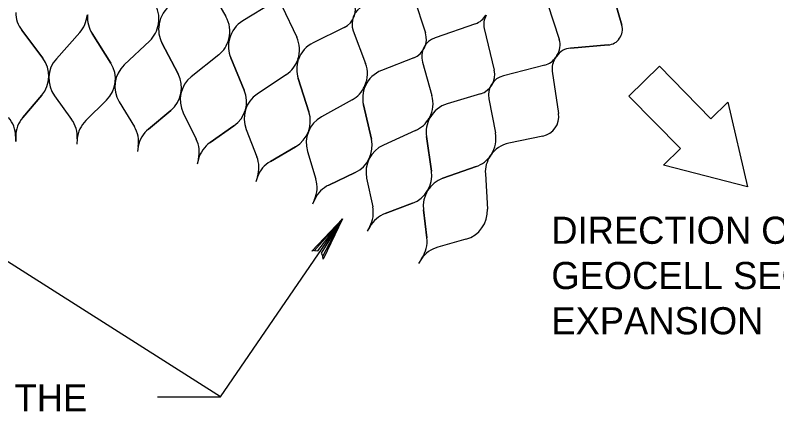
# Model space of a CAD drawing. Extents: x 638850 to 644908, y 297188 to 298900.
# Drawn here: x 639845 to 639929, y 297601.9 to 297645.7 of the extents above; entities that cross this region are included whole.
import ezdxf

# ---------------------------------------------------------------- set-up
doc = ezdxf.new("R2010")
doc.units = 0
for name, color, linetype in [('1', 7, 'Continuous'), ('5', 7, 'Continuous'), ('50', 7, 'Continuous'), ('9', 7, 'Continuous')]:
    doc.layers.add(name, color=color, linetype=linetype)

msp = doc.modelspace()

# ---------------------------------------------------------------- linework, layer by layer
at = {"layer": '1'}
for p, q in [((639912.726, 297636.791), (639916.097, 297640.09)), ((639916.097, 297640.09), (639921.772, 297634.291)), ((639918.401, 297630.992), (639912.726, 297636.791)), ((639921.772, 297634.291), (639923.631, 297636.109)), ((639923.631, 297636.109), (639925.827, 297626.776)), ((639916.543, 297629.173), (639918.401, 297630.992)), ((639925.827, 297626.776), (639916.543, 297629.173)), ((639867.623, 297603.567), (639828.475, 297628.426)), ((639867.623, 297603.567), (639881.085, 297623.21))]:
    msp.add_line(p, q, dxfattribs=at)
msp.add_lwpolyline([(639877.999, 297619.732), (639878.372, 297619.685), (639881.085, 297623.21), (639877.999, 297619.732), (639877.698, 297619.651), (639881.085, 297623.21), (639878.757, 297619.425), (639878.938, 297619.105), (639881.085, 297623.21), (639878.979, 297618.774), (639878.938, 297619.105)], dxfattribs=at)
at = {"layer": '5'}
for p, q in [((639866.298, 297648.885), (639868.226, 297645.577)), ((639910.637, 297649.22), (639911.94, 297644.624)), ((639888.786, 297648.253), (639890.254, 297643.762)), ((639873.371, 297647.079), (639870.093, 297645.101)), ((639874.398, 297646.77), (639876.043, 297643.313)), ((639903.722, 297647.025), (639905.018, 297643.066)), ((639852.903, 297645.762), (639852.898, 297645.702)), ((639852.967, 297645.757), (639852.962, 297645.697)), ((639860.789, 297644.78), (639860.779, 297644.721)), ((639860.853, 297644.77), (639860.843, 297644.711)), ((639895.783, 297644.79), (639891.322, 297643.233)), ((639845.682, 297644.075), (639848.022, 297640.978)), ((639852.089, 297643.816), (639849.507, 297640.918)), ((639881.295, 297644.379), (639877.864, 297642.682)), ((639882.293, 297643.985), (639883.642, 297640.402)), ((639896.755, 297644.258), (639897.841, 297639.659)), ((639853.452, 297643.704), (639855.524, 297640.422)), ((639868.566, 297643.142), (639868.551, 297643.084)), ((639868.628, 297643.126), (639868.613, 297643.068)), ((639859.815, 297642.91), (639856.999, 297640.238)), ((639861.164, 297642.684), (639862.954, 297639.239)), ((639910.423, 297642.436), (639906.272, 297642.095)), ((639867.438, 297641.359), (639864.409, 297638.932)), ((639868.763, 297641.021), (639870.259, 297637.439)), ((639876.177, 297640.858), (639876.158, 297640.801)), ((639876.238, 297640.837), (639876.218, 297640.78)), ((639888.966, 297641.024), (639885.404, 297639.621)), ((639889.927, 297640.549), (639890.972, 297636.866)), ((639904.653, 297641.078), (639904.587, 297640.979)), ((639904.776, 297641.279), (639904.644, 297641.08)), ((639904.719, 297641.178), (639904.653, 297641.078)), ((639903.437, 297640.221), (639898.861, 297639.043)), ((639874.904, 297639.176), (639871.682, 297637.011)), ((639904.264, 297639.533), (639904.954, 297634.859)), ((639876.196, 297638.728), (639877.387, 297635.033)), ((639883.571, 297637.944), (639883.547, 297637.89)), ((639883.63, 297637.918), (639883.605, 297637.864)), ((639847.897, 297636.876), (639845.8, 297634.425)), ((639849.301, 297636.819), (639851.193, 297634.207)), ((639855.057, 297636.344), (639852.762, 297634.078)), ((639882.162, 297636.375), (639878.77, 297634.488)), ((639896.329, 297637.04), (639892.662, 297635.939)), ((639897.247, 297636.485), (639897.979, 297632.727)), ((639856.45, 297636.17), (639858.118, 297633.41)), ((639883.412, 297635.82), (639884.288, 297632.039)), ((639862.147, 297635.216), (639859.67, 297633.149)), ((639863.521, 297634.925), (639864.951, 297632.035)), ((639890.695, 297634.422), (639890.666, 297634.37)), ((639890.751, 297634.391), (639890.722, 297634.339)), ((639869.117, 297633.497), (639866.476, 297631.645)), ((639870.462, 297633.093), (639871.645, 297630.092)), ((639889.159, 297632.976), (639885.621, 297631.38)), ((639845.011, 297632.346), (639845.017, 297631.758)), ((639845.022, 297632.347), (639845.017, 297631.758)), ((639851.801, 297632.073), (639851.758, 297631.486)), ((639851.813, 297632.072), (639851.758, 297631.486)), ((639890.358, 297632.319), (639890.915, 297628.477)), ((639903.224, 297632.378), (639899.476, 297631.594)), ((639858.545, 297631.232), (639858.453, 297630.65)), ((639858.556, 297631.23), (639858.453, 297630.65)), ((639875.919, 297631.201), (639873.133, 297629.577)), ((639877.226, 297630.685), (639878.153, 297627.596)), ((639865.194, 297629.829), (639865.054, 297629.257)), ((639865.206, 297629.826), (639865.054, 297629.257)), ((639897.44, 297630.215), (639897.407, 297630.165)), ((639895.847, 297629.004), (639892.188, 297627.709)), ((639871.703, 297627.874), (639871.516, 297627.316)), ((639871.714, 297627.87), (639871.516, 297627.316)), ((639882.505, 297628.343), (639879.592, 297626.958)), ((639896.872, 297628.184), (639897.099, 297624.309)), ((639883.764, 297627.72), (639884.43, 297624.564)), ((639878.025, 297625.381), (639877.792, 297624.84)), ((639878.036, 297625.376), (639877.792, 297624.84)), ((639888.828, 297624.944), (639885.81, 297623.807)), ((639890.031, 297624.217), (639890.416, 297621.128)), ((639884.116, 297622.367), (639883.838, 297621.848)), ((639884.126, 297622.361), (639883.838, 297621.848)), ((639894.719, 297620.966), (639891.614, 297620.091)), ((639889.813, 297618.794), (639889.483, 297618.307))]:
    msp.add_line(p, q, dxfattribs=at)
for centre, radius, start, end in [((639857.595, 297645.318), 3.24, 350.44021, 35.04845), ((639880.318, 297646.356), 2.206, 296.31108, 22.90015), ((639864.048, 297644.237), 3.24, 125.91822, 170.52646), ((639884.357, 297644.763), 2.206, 114.04867, 200.63774), ((639848.267, 297646.028), 3.24, 180.1336, 217.07193), ((639849.67, 297645.971), 3.24, 318.30545, 355.24378), ((639856.191, 297645.433), 3.24, 175.33003, 212.26836), ((639865.427, 297643.946), 3.24, 345.63664, 30.24488), ((639895.102, 297646.743), 2.068, 289.2451, 331.22593), ((639898.767, 297644.733), 2.068, 151.31218, 193.29301), ((639857.585, 297645.259), 3.24, 313.50188, 350.44021), ((639864.038, 297644.178), 3.24, 170.52646, 207.46479), ((639871.767, 297642.327), 3.24, 121.11465, 165.72289), ((639910.282, 297644.154), 1.723, 274.70429, 15.82869), ((639865.412, 297643.888), 3.24, 308.69831, 345.63664), ((639871.753, 297642.269), 3.24, 165.72289, 202.66122), ((639873.117, 297641.921), 3.24, 340.83307, 25.44131), ((639888.157, 297643.077), 2.206, 291.50751, 18.09658), ((639892.049, 297641.151), 2.206, 109.2451, 195.83416), ((639903.053, 297642.422), 2.068, 326.42236, 18.13587), ((639879.299, 297639.778), 3.24, 116.31108, 160.91932), ((639906.441, 297640.034), 2.068, 94.70429, 146.4178), ((639845.409, 297639.004), 3.274, 319.44945, 37.07193), ((639851.952, 297638.74), 3.274, 138.30545, 215.92793), ((639873.098, 297641.865), 3.24, 303.89474, 340.83307), ((639879.28, 297639.721), 3.24, 160.91932, 197.85765), ((639902.922, 297642.224), 2.068, 284.44152, 326.42236), ((639906.31, 297639.835), 2.068, 146.4178, 188.39863), ((639852.756, 297638.674), 3.274, 314.64588, 32.26836), ((639859.253, 297637.863), 3.274, 133.50188, 211.12436), ((639880.611, 297639.261), 3.24, 336.0295, 20.63773), ((639886.592, 297636.607), 3.24, 111.50751, 156.11575), ((639895.695, 297639.152), 2.206, 286.70394, 13.29301), ((639860.049, 297637.729), 3.274, 309.84231, 27.46479), ((639866.456, 297636.377), 3.274, 128.69831, 206.32079), ((639899.412, 297636.907), 2.206, 104.44153, 191.03059), ((639867.237, 297636.178), 3.274, 305.03874, 22.66122), ((639880.586, 297639.206), 3.24, 299.09117, 336.0295), ((639886.567, 297636.552), 3.24, 156.11575, 193.05408), ((639873.508, 297634.294), 3.274, 123.89474, 201.51722), ((639887.855, 297635.982), 3.24, 331.22593, 15.83416), ((639893.593, 297632.836), 3.24, 106.70394, 151.31217), ((639874.27, 297634.029), 3.274, 300.23517, 17.85765), ((639902.772, 297634.537), 2.206, 281.80956, 8.39863), ((639841.771, 297632.309), 3.24, 0.66838, 40.7315), ((639848.262, 297632.319), 3.24, 139.44945, 179.51256), ((639848.57, 297632.307), 3.24, 355.86481, 35.92793), ((639855.039, 297631.773), 3.24, 134.64588, 174.70899), ((639880.361, 297631.627), 3.274, 119.09117, 196.71365), ((639887.826, 297635.929), 3.24, 294.2876, 331.22593), ((639893.564, 297632.784), 3.24, 151.31218, 188.2505), ((639855.344, 297631.735), 3.24, 351.06124, 31.12436), ((639861.746, 297630.662), 3.24, 129.84231, 169.90542), ((639862.047, 297630.598), 3.24, 346.25767, 26.32079), ((639881.099, 297631.3), 3.274, 295.4316, 13.05408), ((639894.799, 297632.107), 3.24, 326.42236, 11.03059), ((639868.336, 297628.993), 3.24, 125.03874, 165.10185), ((639886.967, 297628.396), 3.274, 114.2876, 191.91008), ((639900.139, 297628.423), 3.24, 101.80956, 146.4178), ((639868.631, 297628.904), 3.24, 341.4541, 21.51722), ((639874.764, 297626.778), 3.24, 120.23517, 160.29828), ((639894.766, 297632.058), 3.24, 289.48403, 326.42235), ((639900.106, 297628.373), 3.24, 146.4178, 183.35613), ((639887.675, 297628.008), 3.274, 290.62803, 8.25051), ((639875.051, 297626.665), 3.24, 336.65053, 16.71365), ((639893.28, 297624.622), 3.274, 109.48403, 187.10651), ((639880.983, 297624.032), 3.24, 115.4316, 155.49471), ((639881.26, 297623.895), 3.24, 331.84696, 11.91008), ((639886.951, 297620.775), 3.24, 110.62803, 150.69114), ((639893.831, 297624.117), 3.274, 285.73365, 3.35613), ((639887.201, 297620.727), 3.24, 325.80132, 7.10651), ((639892.493, 297616.973), 3.24, 105.73365, 145.79676)]:
    msp.add_arc(centre, radius, start, end, dxfattribs=at)
at = {"layer": '50'}
for p, q in [((639911.94, 297644.624), (639910.637, 297649.22)), ((639903.722, 297647.025), (639905.018, 297643.066)), ((639852.962, 297645.697), (639852.898, 297645.702)), ((639860.843, 297644.711), (639860.779, 297644.721)), ((639848.022, 297640.978), (639845.682, 297644.075)), ((639852.089, 297643.816), (639849.507, 297640.918)), ((639855.524, 297640.422), (639853.452, 297643.704)), ((639868.613, 297643.068), (639868.551, 297643.084)), ((639859.815, 297642.91), (639856.999, 297640.238)), ((639862.954, 297639.239), (639861.164, 297642.684)), ((639906.272, 297642.095), (639910.423, 297642.436)), ((639867.438, 297641.359), (639864.409, 297638.932)), ((639870.259, 297637.439), (639868.763, 297641.021)), ((639876.218, 297640.78), (639876.158, 297640.801)), ((639904.776, 297641.279), (639904.644, 297641.08)), ((639904.644, 297641.08), (639904.653, 297641.078)), ((639904.653, 297641.078), (639904.719, 297641.178)), ((639874.904, 297639.176), (639871.682, 297637.011)), ((639877.387, 297635.033), (639876.196, 297638.728)), ((639883.605, 297637.864), (639883.547, 297637.89)), ((639845.8, 297634.425), (639847.897, 297636.876)), ((639849.301, 297636.819), (639851.193, 297634.207)), ((639852.762, 297634.078), (639855.057, 297636.344)), ((639882.162, 297636.375), (639878.77, 297634.488)), ((639856.45, 297636.17), (639858.118, 297633.41)), ((639884.288, 297632.039), (639883.412, 297635.82)), ((639859.67, 297633.149), (639862.147, 297635.216)), ((639863.521, 297634.925), (639864.951, 297632.035)), ((639890.722, 297634.339), (639890.666, 297634.37)), ((639866.476, 297631.645), (639869.117, 297633.497)), ((639870.462, 297633.093), (639871.645, 297630.092)), ((639889.159, 297632.976), (639885.621, 297631.38)), ((639845.011, 297632.346), (639845.017, 297631.758)), ((639845.017, 297631.758), (639845.022, 297632.347)), ((639890.915, 297628.477), (639890.358, 297632.319)), ((639873.133, 297629.577), (639875.919, 297631.201)), ((639877.226, 297630.685), (639878.153, 297627.596)), ((639897.465, 297630.266), (639897.407, 297630.165)), ((639892.188, 297627.709), (639895.847, 297629.004)), ((639879.592, 297626.958), (639882.505, 297628.343)), ((639896.872, 297628.184), (639897.099, 297624.309)), ((639883.764, 297627.72), (639884.43, 297624.564)), ((639885.81, 297623.807), (639888.828, 297624.944)), ((639890.416, 297621.128), (639890.031, 297624.217)), ((639894.719, 297620.966), (639891.614, 297620.091)), ((639889.813, 297618.794), (639889.881, 297618.906))]:
    msp.add_line(p, q, dxfattribs=at)
for centre, radius, start, end in [((639848.267, 297646.028), 3.24, 180.1336, 217.07193), ((639849.67, 297645.971), 3.24, 318.30545, 355.24378), ((639856.191, 297645.433), 3.24, 175.33003, 212.26835), ((639857.585, 297645.259), 3.24, 313.50188, 350.44021), ((639864.038, 297644.178), 3.24, 170.52646, 207.46479), ((639910.282, 297644.154), 1.723, 274.70429, 15.82868), ((639865.412, 297643.888), 3.24, 308.69831, 345.63664), ((639871.753, 297642.269), 3.24, 165.72289, 202.66122), ((639903.053, 297642.422), 2.068, 326.42236, 18.13587), ((639906.441, 297640.034), 2.068, 94.70429, 146.4178), ((639845.409, 297639.004), 3.274, 319.44945, 37.07193), ((639851.952, 297638.74), 3.274, 138.30545, 215.92793), ((639873.098, 297641.865), 3.24, 303.89474, 340.83307), ((639879.28, 297639.721), 3.24, 160.91932, 197.85765), ((639852.756, 297638.674), 3.274, 314.64588, 32.26835), ((639859.253, 297637.863), 3.274, 133.50188, 211.12436), ((639860.049, 297637.729), 3.274, 309.84231, 27.46479), ((639866.456, 297636.377), 3.274, 128.69831, 206.32079), ((639867.237, 297636.178), 3.274, 305.03874, 22.66122), ((639880.586, 297639.206), 3.24, 299.09117, 336.0295), ((639886.567, 297636.552), 3.24, 156.11575, 193.05407), ((639873.508, 297634.294), 3.274, 123.89474, 201.51722), ((639874.27, 297634.029), 3.274, 300.23517, 17.85764), ((639841.771, 297632.309), 3.24, 0.66838, 40.7315), ((639848.262, 297632.319), 3.24, 139.44945, 179.51256), ((639848.57, 297632.307), 3.24, 355.86481, 35.92793), ((639855.039, 297631.773), 3.24, 134.64588, 174.70899), ((639880.361, 297631.627), 3.274, 119.09117, 196.71365), ((639887.826, 297635.929), 3.24, 294.2876, 331.22593), ((639893.564, 297632.784), 3.24, 151.31218, 188.25051), ((639855.344, 297631.735), 3.24, 351.06124, 31.12436), ((639861.746, 297630.662), 3.24, 129.84231, 169.90543), ((639862.047, 297630.598), 3.24, 346.25767, 26.32079), ((639881.099, 297631.3), 3.274, 295.4316, 13.05407), ((639868.336, 297628.993), 3.24, 125.03874, 165.10185), ((639886.967, 297628.396), 3.274, 114.2876, 191.91008), ((639868.631, 297628.904), 3.24, 341.4541, 21.51722), ((639874.764, 297626.778), 3.24, 120.23517, 160.29828), ((639894.766, 297632.058), 3.24, 289.48403, 326.42235), ((639900.106, 297628.373), 3.24, 146.4178, 183.35613), ((639887.675, 297628.008), 3.274, 290.62803, 8.25051), ((639875.051, 297626.665), 3.24, 336.65053, 16.71365), ((639893.28, 297624.622), 3.274, 109.48403, 187.10651), ((639880.983, 297624.032), 3.24, 115.4316, 155.49471), ((639881.26, 297623.895), 3.24, 331.84696, 11.91008), ((639886.951, 297620.775), 3.24, 110.62803, 150.69114), ((639893.831, 297624.117), 3.274, 285.73365, 3.35613), ((639887.201, 297620.727), 3.24, 325.80132, 7.10651), ((639892.493, 297616.973), 3.24, 105.73365, 145.79676)]:
    msp.add_arc(centre, radius, start, end, dxfattribs=at)
at = {"layer": '9'}
msp.add_line((639860.687, 297603.567), (639867.623, 297603.567), dxfattribs=at)

# ---------------------------------------------------------------- texts
at = {"layer": '1'}
for s, p in [('DIRECTION OF', (639904.155, 297620.467)), ('GEOCELL SECTION', (639904.155, 297615.467)), ('EXPANSION', (639904.155, 297610.467)), ('UNDER-EXPAND THE', (639811.688, 297601.951))]:
    msp.add_text(s, height=3, dxfattribs=at).set_placement(p)

doc.saveas('drawing.dxf')
